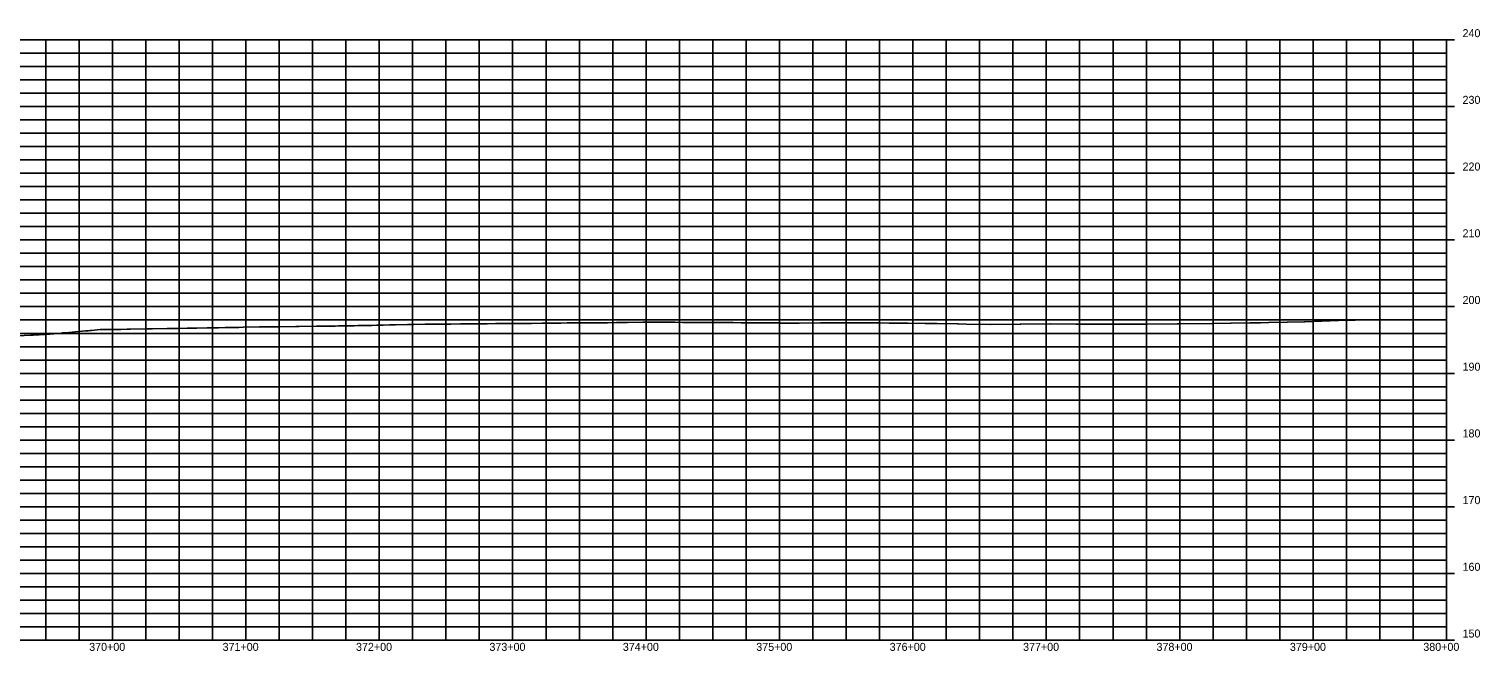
# Model space of a CAD drawing. Extents: x 1399671 to 1408349, y 1930471 to 1933387.
# Drawn here: x 1407262 to 1408349, y 1931271 to 1931737 of the extents above; entities that cross this region are included whole.
import ezdxf

# ---------------------------------------------------------------- set-up
doc = ezdxf.new("R2010")
doc.units = 0
for name, color, linetype in [('R_Exist Surface', 7, 'Continuous'), ('R_Grid', 7, 'Continuous'), ('R_Grid Annot', 7, 'Continuous')]:
    doc.layers.add(name, color=color, linetype=linetype)

msp = doc.modelspace()

# ---------------------------------------------------------------- linework, layer by layer
at = {"layer": 'R_Exist Surface'}
msp.add_lwpolyline([(1407253.1, 1931506.7), (1407263, 1931507.2), (1407264.9, 1931507.3), (1407269.4, 1931507.6), (1407277.2, 1931508.1), (1407286.4, 1931508.8), (1407286.8, 1931508.9), (1407291.6, 1931509.3), (1407304, 1931510.4), (1407306.1, 1931510.6), (1407307.6, 1931510.7), (1407308.6, 1931510.8), (1407315.1, 1931511.4), (1407320.7, 1931511.5), (1407321.3, 1931511.5), (1407330.5, 1931511.6), (1407335.2, 1931511.7), (1407337.7, 1931511.7), (1407350.3, 1931511.9), (1407352.3, 1931512), (1407354.3, 1931512), (1407365.3, 1931512.2), (1407370.9, 1931512.3), (1407374.2, 1931512.3), (1407380.2, 1931512.4), (1407387.6, 1931512.6), (1407395.2, 1931512.7), (1407396, 1931512.7), (1407403.6, 1931512.8), (1407408.8, 1931512.9), (1407417.9, 1931513.1), (1407419, 1931513.1), (1407422.3, 1931513.2), (1407434.4, 1931513.4), (1407435.7, 1931513.4), (1407439.7, 1931513.5), (1407445.7, 1931513.6), (1407449.2, 1931513.6), (1407449.4, 1931513.6), (1407461.6, 1931513.8), (1407463.2, 1931513.8), (1407464.2, 1931513.8), (1407477.2, 1931514), (1407478.9, 1931514), (1407483.4, 1931514), (1407491.2, 1931514.1), (1407493.7, 1931514.2), (1407505.1, 1931514.3), (1407505.3, 1931514.3), (1407508.2, 1931514.4), (1407518.6, 1931514.6), (1407522.3, 1931514.7), (1407527.1, 1931514.8), (1407532, 1931514.9), (1407536.3, 1931515), (1407545.3, 1931515.2), (1407549, 1931515.3), (1407550.2, 1931515.3), (1407558.7, 1931515.5), (1407564.2, 1931515.5), (1407570.8, 1931515.6), (1407571.8, 1931515.6), (1407577.8, 1931515.6), (1407585, 1931515.7), (1407591.4, 1931515.7), (1407592.7, 1931515.8), (1407598.2, 1931515.8), (1407605.1, 1931515.8), (1407611.4, 1931515.9), (1407614.5, 1931515.9), (1407618.7, 1931516), (1407624.8, 1931516), (1407632.6, 1931516.1), (1407636.4, 1931516.1), (1407638.3, 1931516.1), (1407646.4, 1931516.2), (1407651.7, 1931516.3), (1407658.2, 1931516.3), (1407660.3, 1931516.3), (1407665.1, 1931516.4), (1407675.3, 1931516.5), (1407680.1, 1931516.5), (1407680.2, 1931516.5), (1407690.8, 1931516.6), (1407695.3, 1931516.6), (1407702, 1931516.7), (1407706.4, 1931516.7), (1407710.4, 1931516.8), (1407721.9, 1931516.9), (1407723.8, 1931516.9), (1407725.5, 1931516.9), (1407736.8, 1931516.9), (1407739.8, 1931516.9), (1407745.7, 1931516.9), (1407751.6, 1931516.8), (1407754.1, 1931516.8), (1407766.4, 1931516.8), (1407767.5, 1931516.8), (1407768.4, 1931516.8), (1407781.2, 1931516.8), (1407782.7, 1931516.7), (1407789.4, 1931516.7), (1407795.4, 1931516.6), (1407796.8, 1931516.6), (1407809.5, 1931516.5), (1407810.8, 1931516.5), (1407811.2, 1931516.5), (1407823.7, 1931516.4), (1407824.9, 1931516.3), (1407833.1, 1931516.3), (1407837.8, 1931516.2), (1407838.9, 1931516.2), (1407854.9, 1931516.4), (1407858.5, 1931516.4), (1407859.2, 1931516.4), (1407874.4, 1931516.6), (1407876.8, 1931516.6), (1407879.5, 1931516.6), (1407879.7, 1931516.6), (1407893, 1931516.5), (1407893.1, 1931516.5), (1407898.6, 1931516.4), (1407906.4, 1931516.3), (1407906.6, 1931516.3), (1407919.8, 1931516.2), (1407920, 1931516.2), (1407920.5, 1931516.2), (1407933.3, 1931516), (1407933.4, 1931516), (1407942.3, 1931515.9), (1407957.7, 1931515.7), (1407958, 1931515.7), (1407958.2, 1931515.7), (1407964.2, 1931515.6), (1407982.3, 1931515.3), (1407982.7, 1931515.3), (1408004.7, 1931515.5), (1408005.1, 1931515.5), (1408027.4, 1931515.7), (1408027.6, 1931515.7), (1408046.4, 1931515.6), (1408046.7, 1931515.6), (1408065.4, 1931515.6), (1408065.8, 1931515.6), (1408066.1, 1931515.6), (1408077.7, 1931515.6), (1408082.4, 1931515.6), (1408098.4, 1931515.5), (1408099, 1931515.5), (1408122.3, 1931515.8), (1408123.9, 1931515.8), (1408123.9, 1931515.8), (1408123.9, 1931515.8), (1408148.3, 1931516), (1408148.8, 1931516), (1408162.5, 1931516.3), (1408162.8, 1931516.3), (1408176.7, 1931516.5), (1408176.8, 1931516.5), (1408184.8, 1931516.6), (1408190.8, 1931516.7), (1408190.9, 1931516.7), (1408204.8, 1931516.9), (1408205.1, 1931516.9), (1408217.5, 1931517.3), (1408217.9, 1931517.3), (1408230.3, 1931517.7), (1408230.7, 1931517.7), (1408243.1, 1931518.1), (1408255.5, 1931518.5), (1408255.9, 1931518.6), (1408264.2, 1931518.8)], dxfattribs=at)
at = {"layer": 'R_Grid'}
for p, q in [((1400324.2, 1931728.6), (1408324.2, 1931728.6)), ((1400324.2, 1931728.6), (1408324.2, 1931728.6)), ((1407274.2, 1931278.6), (1407274.2, 1931728.6)), ((1407299.2, 1931278.6), (1407299.2, 1931728.6)), ((1407324.2, 1931278.6), (1407324.2, 1931728.6)), ((1407349.2, 1931278.6), (1407349.2, 1931728.6)), ((1407374.2, 1931278.6), (1407374.2, 1931728.6)), ((1407399.2, 1931278.6), (1407399.2, 1931728.6)), ((1407424.2, 1931278.6), (1407424.2, 1931728.6)), ((1407449.2, 1931278.6), (1407449.2, 1931728.6)), ((1407474.2, 1931278.6), (1407474.2, 1931728.6)), ((1407499.2, 1931278.6), (1407499.2, 1931728.6)), ((1407524.2, 1931278.6), (1407524.2, 1931728.6)), ((1407549.2, 1931278.6), (1407549.2, 1931728.6)), ((1407574.2, 1931278.6), (1407574.2, 1931728.6)), ((1407599.2, 1931278.6), (1407599.2, 1931728.6)), ((1407624.2, 1931278.6), (1407624.2, 1931728.6)), ((1407649.2, 1931278.6), (1407649.2, 1931728.6)), ((1407674.2, 1931278.6), (1407674.2, 1931728.6)), ((1407699.2, 1931278.6), (1407699.2, 1931728.6)), ((1407724.2, 1931278.6), (1407724.2, 1931728.6)), ((1407749.2, 1931278.6), (1407749.2, 1931728.6)), ((1407774.2, 1931278.6), (1407774.2, 1931728.6)), ((1407799.2, 1931278.6), (1407799.2, 1931728.6)), ((1407824.2, 1931278.6), (1407824.2, 1931728.6)), ((1407849.2, 1931278.6), (1407849.2, 1931728.6)), ((1407874.2, 1931278.6), (1407874.2, 1931728.6)), ((1407899.2, 1931278.6), (1407899.2, 1931728.6)), ((1407924.2, 1931278.6), (1407924.2, 1931728.6)), ((1407949.2, 1931278.6), (1407949.2, 1931728.6)), ((1407974.2, 1931278.6), (1407974.2, 1931728.6)), ((1407999.2, 1931278.6), (1407999.2, 1931728.6)), ((1408024.2, 1931278.6), (1408024.2, 1931728.6)), ((1408049.2, 1931278.6), (1408049.2, 1931728.6)), ((1408074.2, 1931278.6), (1408074.2, 1931728.6)), ((1408099.2, 1931278.6), (1408099.2, 1931728.6)), ((1408124.2, 1931278.6), (1408124.2, 1931728.6)), ((1408149.2, 1931278.6), (1408149.2, 1931728.6)), ((1408174.2, 1931278.6), (1408174.2, 1931728.6)), ((1408199.2, 1931278.6), (1408199.2, 1931728.6)), ((1408224.2, 1931278.6), (1408224.2, 1931728.6)), ((1408249.2, 1931278.6), (1408249.2, 1931728.6)), ((1408274.2, 1931278.6), (1408274.2, 1931728.6)), ((1408299.2, 1931278.6), (1408299.2, 1931728.6)), ((1408324.2, 1931278.6), (1408324.2, 1931728.6)), ((1400324.2, 1931718.6), (1408324.2, 1931718.6)), ((1400324.2, 1931708.6), (1408324.2, 1931708.6)), ((1400324.2, 1931698.6), (1408324.2, 1931698.6)), ((1400324.2, 1931688.6), (1408324.2, 1931688.6)), ((1400324.2, 1931678.6), (1408324.2, 1931678.6)), ((1400324.2, 1931668.6), (1408324.2, 1931668.6)), ((1400324.2, 1931658.6), (1408324.2, 1931658.6)), ((1400324.2, 1931648.6), (1408324.2, 1931648.6)), ((1400324.2, 1931638.6), (1408324.2, 1931638.6)), ((1400324.2, 1931628.6), (1408324.2, 1931628.6)), ((1400324.2, 1931618.6), (1408324.2, 1931618.6)), ((1400324.2, 1931608.6), (1408324.2, 1931608.6)), ((1400324.2, 1931598.6), (1408324.2, 1931598.6)), ((1400324.2, 1931588.6), (1408324.2, 1931588.6)), ((1400324.2, 1931578.6), (1408324.2, 1931578.6)), ((1400324.2, 1931568.6), (1408324.2, 1931568.6)), ((1400324.2, 1931558.6), (1408324.2, 1931558.6)), ((1400324.2, 1931548.6), (1408324.2, 1931548.6)), ((1400324.2, 1931538.6), (1408324.2, 1931538.6)), ((1400324.2, 1931528.6), (1408324.2, 1931528.6)), ((1400324.2, 1931518.6), (1408324.2, 1931518.6)), ((1400324.2, 1931508.6), (1408324.2, 1931508.6)), ((1400324.2, 1931498.6), (1408324.2, 1931498.6)), ((1400324.2, 1931488.6), (1408324.2, 1931488.6)), ((1400324.2, 1931478.6), (1408324.2, 1931478.6)), ((1400324.2, 1931468.6), (1408324.2, 1931468.6)), ((1400324.2, 1931458.6), (1408324.2, 1931458.6)), ((1400324.2, 1931448.6), (1408324.2, 1931448.6)), ((1400324.2, 1931438.6), (1408324.2, 1931438.6)), ((1400324.2, 1931428.6), (1408324.2, 1931428.6)), ((1400324.2, 1931418.6), (1408324.2, 1931418.6)), ((1400324.2, 1931408.6), (1408324.2, 1931408.6)), ((1400324.2, 1931398.6), (1408324.2, 1931398.6)), ((1400324.2, 1931388.6), (1408324.2, 1931388.6)), ((1400324.2, 1931378.6), (1408324.2, 1931378.6)), ((1400324.2, 1931368.6), (1408324.2, 1931368.6)), ((1400324.2, 1931358.6), (1408324.2, 1931358.6)), ((1400324.2, 1931348.6), (1408324.2, 1931348.6)), ((1400324.2, 1931338.6), (1408324.2, 1931338.6)), ((1400324.2, 1931328.6), (1408324.2, 1931328.6)), ((1400324.2, 1931318.6), (1408324.2, 1931318.6)), ((1400324.2, 1931308.6), (1408324.2, 1931308.6)), ((1400324.2, 1931298.6), (1408324.2, 1931298.6)), ((1400324.2, 1931288.6), (1408324.2, 1931288.6)), ((1400324.2, 1931278.6), (1408324.2, 1931278.6))]:
    msp.add_line(p, q, dxfattribs=at)
at = {"layer": 'R_Grid Annot'}
for p, q in [((1408330.2, 1931728.6), (1408324.2, 1931728.6)), ((1408330.2, 1931728.6), (1408324.2, 1931728.6)), ((1408324.2, 1931718.6), (1408321.2, 1931718.6)), ((1408324.2, 1931708.6), (1408321.2, 1931708.6)), ((1408324.2, 1931698.6), (1408321.2, 1931698.6)), ((1408324.2, 1931688.6), (1408321.2, 1931688.6)), ((1408330.2, 1931678.6), (1408324.2, 1931678.6)), ((1408324.2, 1931668.6), (1408321.2, 1931668.6)), ((1408324.2, 1931658.6), (1408321.2, 1931658.6)), ((1408324.2, 1931648.6), (1408321.2, 1931648.6)), ((1408324.2, 1931638.6), (1408321.2, 1931638.6)), ((1408330.2, 1931628.6), (1408324.2, 1931628.6)), ((1408324.2, 1931618.6), (1408321.2, 1931618.6)), ((1408324.2, 1931608.6), (1408321.2, 1931608.6)), ((1408324.2, 1931598.6), (1408321.2, 1931598.6)), ((1408324.2, 1931588.6), (1408321.2, 1931588.6)), ((1408330.2, 1931578.6), (1408324.2, 1931578.6)), ((1408324.2, 1931568.6), (1408321.2, 1931568.6)), ((1408324.2, 1931558.6), (1408321.2, 1931558.6)), ((1408324.2, 1931548.6), (1408321.2, 1931548.6)), ((1408324.2, 1931538.6), (1408321.2, 1931538.6)), ((1408330.2, 1931528.6), (1408324.2, 1931528.6)), ((1408324.2, 1931518.6), (1408321.2, 1931518.6)), ((1408324.2, 1931508.6), (1408321.2, 1931508.6)), ((1408324.2, 1931498.6), (1408321.2, 1931498.6)), ((1408324.2, 1931488.6), (1408321.2, 1931488.6)), ((1408330.2, 1931478.6), (1408324.2, 1931478.6)), ((1408324.2, 1931468.6), (1408321.2, 1931468.6)), ((1408324.2, 1931458.6), (1408321.2, 1931458.6)), ((1408324.2, 1931448.6), (1408321.2, 1931448.6)), ((1408324.2, 1931438.6), (1408321.2, 1931438.6)), ((1408330.2, 1931428.6), (1408324.2, 1931428.6)), ((1408324.2, 1931418.6), (1408321.2, 1931418.6)), ((1408324.2, 1931408.6), (1408321.2, 1931408.6)), ((1408324.2, 1931398.6), (1408321.2, 1931398.6)), ((1408324.2, 1931388.6), (1408321.2, 1931388.6)), ((1408330.2, 1931378.6), (1408324.2, 1931378.6)), ((1408324.2, 1931368.6), (1408321.2, 1931368.6)), ((1408324.2, 1931358.6), (1408321.2, 1931358.6)), ((1408324.2, 1931348.6), (1408321.2, 1931348.6)), ((1408324.2, 1931338.6), (1408321.2, 1931338.6)), ((1408330.2, 1931328.6), (1408324.2, 1931328.6)), ((1408324.2, 1931318.6), (1408321.2, 1931318.6)), ((1408324.2, 1931308.6), (1408321.2, 1931308.6)), ((1408324.2, 1931298.6), (1408321.2, 1931298.6)), ((1408324.2, 1931288.6), (1408321.2, 1931288.6)), ((1408330.2, 1931278.6), (1408324.2, 1931278.6))]:
    msp.add_line(p, q, dxfattribs=at)

# ---------------------------------------------------------------- texts
for s, p in [('240', (1408336.2, 1931730.6)), ('240', (1408336.2, 1931730.6)), ('230', (1408336.2, 1931680.6)), ('220', (1408336.2, 1931630.6)), ('210', (1408336.2, 1931580.6)), ('200', (1408336.2, 1931530.6)), ('190', (1408336.2, 1931480.6)), ('180', (1408336.2, 1931430.6)), ('170', (1408336.2, 1931380.6)), ('160', (1408336.2, 1931330.6)), ('150', (1408336.2, 1931280.6)), ('370+00', (1407306.8, 1931270.6)), ('371+00', (1407406.8, 1931270.6)), ('372+00', (1407506.8, 1931270.6)), ('373+00', (1407606.8, 1931270.6)), ('374+00', (1407706.8, 1931270.6)), ('375+00', (1407806.8, 1931270.6)), ('376+00', (1407906.8, 1931270.6)), ('377+00', (1408006.8, 1931270.6)), ('378+00', (1408106.8, 1931270.6)), ('379+00', (1408206.8, 1931270.6)), ('380+00', (1408306.8, 1931270.6))]:
    msp.add_text(s, height=6, dxfattribs=at).set_placement(p)

doc.saveas('drawing.dxf')
